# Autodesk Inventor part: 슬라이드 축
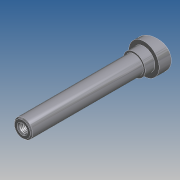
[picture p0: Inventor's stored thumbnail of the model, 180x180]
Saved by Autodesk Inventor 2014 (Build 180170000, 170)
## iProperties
Company: 한국ATC센터
Created: 2012-05
Part Number: 슬라이드 축
Document SubType Name: 모델링
Designer: KYOUNG IL JANG
Mass: 169.563 g
Surface Area: 67.586 cm^2
Volume: 21.5729 cm^3
Density: 7.86 g/cm^3
Material: 강, 연강
Appearance: 강철
변환 표준: STEP AP214IS
파일 이름: C:\Users\SeoGD\Desktop\?쒗뿕\異?stp
전처리기: Build: 253, Release: 2010 SP1 - Date: Wed 07/29/2009
전송 단위: 밀리미터
불확실성: 0.01
Author: KYOUNG IL JANG
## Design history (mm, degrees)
sketch "스케치1"
  geometry: L1 (0, 100)-(7.5, 100); L2 (7.5, 100)-(7.5, 0); L3 (7.5, 0)-(12.5, 0); L4 (12.5, 0)-(12.5, -17); L5 (12.5, -17)-(0, -17); L6 (0, -17)-(0, 100); 1 further point
  constraints: 12 end point, 2 parallel, 2 point on line, 1 perpendicular, 1 vertical
  dimensions: "d0" = 100 distance from line of L1 point (0, 0); "d1" = 15 diameter of L2 L6; "d2" = 25 diameter of L4 L6; "d3" = 17 distance of L3.end L4.end
revolve "회전1" sketch "스케치1" stored, may be unused: angle "d4" = 90 deg
sketch "스케치2"
  geometry: L1 (12.5, 0)-(12.5, -17) reference; L2 (-12.5, -17)-(12.5, -17) reference; L3 (-12.5, 0)-(-12.5, -17) reference; L4 (12.5, -5)-(-12.5, -11.699); L5 (-12.5, 0)-(12.5, 0) reference; 1 further point
  constraints: 2 end point, 2 point on line
  dimensions: "d5" = 75 deg angle of L1 L4; "d6" = 5 distance from line of L4.start L5
extrude "돌출1" cut sketch "스케치2" stored distance "d7" = 10; taper "d8" = 0 deg
chamfer "모따기1" distance "d9" = 1; stored, may be unused: second distance "d10" = 2, angle "d11" = 45 deg
fillet "모깎기1" dims "d12" = 0.5
hole "구멍1" diameter "d15" = 6.647; stored, may be unused: countersink angle "d19" = 90 deg, drill point angle "d21" = 118 deg; dims "d13" = 10, "d14" = 10, "d16" = 17, "d17" = 4, "d18" = 2, "d20" = 20
chamfer "모따기2" distance "d22" = 1; stored, may be unused: second distance "d23" = 2, angle "d24" = 45 deg
sketch "스케치3"
  geometry: C1 r 9 at (0, 0); 1 further point
  constraints: 1 centre point, 1 coincident
  dimensions: "d25" = 18 diameter of C1
extrude "돌출2" join sketch "스케치3" distance "d26" = 8; taper "d27" = 0 deg
node "솔리드1"
node "솔리드 본체"
node "곡면 본체"
node "솔리드2"
